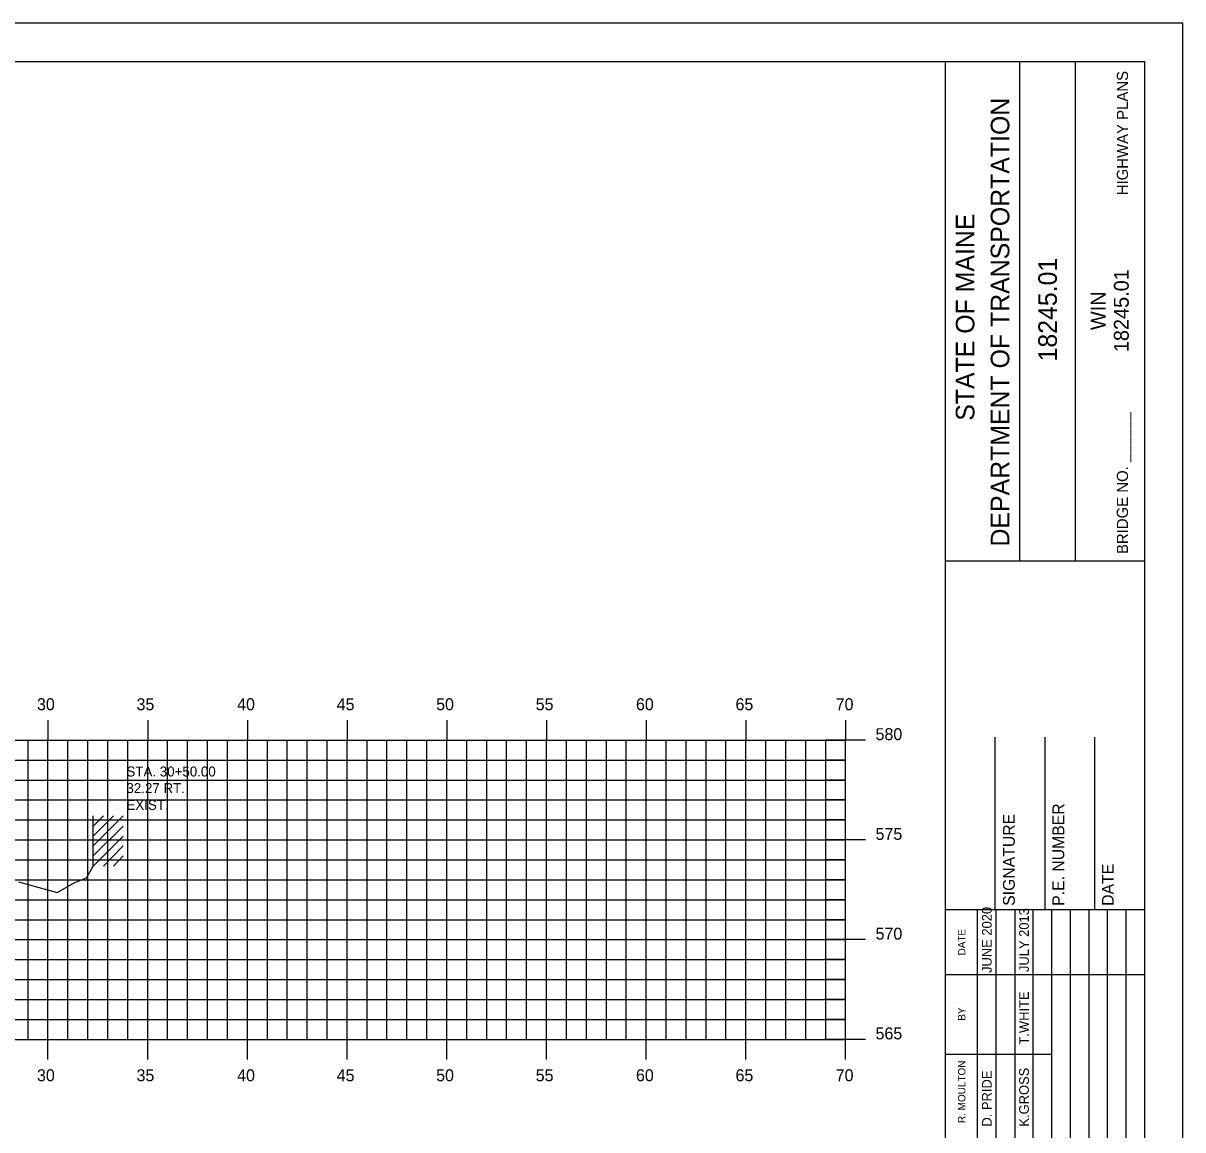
# Model space of a CAD drawing. Extents: x 1048109 to 1048279, y 781630 to 781740.
# Drawn here: x 1048220.5 to 1048278.6, y 781684.7 to 781740.1 of the extents above; entities that cross this region are included whole.
import ezdxf

# ---------------------------------------------------------------- set-up
doc = ezdxf.new("R2010")
doc.units = 0
for name, color, linetype in [('BORDER', 7, 'Continuous'), ('D_Text_Monospaced', 7, 'Continuous'), ('Default', 7, 'Continuous'), ('H_V ANNOTATION', 7, 'Continuous'), ('MAJOR', 7, 'Continuous'), ('MINOR', 7, 'Continuous'), ('S_Buildings', 7, 'Continuous'), ('S_Roadway_Centerline', 7, 'Continuous')]:
    doc.layers.add(name, color=color, linetype=linetype)

msp = doc.modelspace()

# ---------------------------------------------------------------- linework, layer by layer
at = {"layer": 'Default'}
for p, q in [((1048276.734, 781738.195), (1048116.734, 781738.195)), ((1048266.734, 781633.195), (1048266.734, 781738.198)), ((1048270.462, 781713.193), (1048270.462, 781738.193)), ((1048273.257, 781713.193), (1048273.257, 781738.193)), ((1048276.734, 781633.195), (1048276.734, 781738.195)), ((1048266.734, 781713.19), (1048276.734, 781713.19)), ((1048269.234, 781695.698), (1048269.234, 781704.346)), ((1048271.734, 781695.698), (1048271.734, 781704.346)), ((1048274.234, 781695.698), (1048274.234, 781704.346)), ((1048266.734, 781695.698), (1048276.734, 781695.698))]:
    msp.add_line(p, q, dxfattribs=at)
msp.add_lwpolyline([(1048108.64, 781630.136), (1048278.64, 781630.136), (1048278.64, 781740.136), (1048108.64, 781740.136)], close=True, dxfattribs=at)
for points in [[(1048268.348, 781692.448), (1048268.348, 781695.698)], [(1048269.281, 781678.201), (1048269.281, 781695.698)], [(1048270.213, 781695.698), (1048270.213, 781678.201)], [(1048271.144, 781678.201), (1048271.144, 781695.698)], [(1048272.076, 781678.201), (1048272.076, 781695.698)], [(1048273.008, 781678.201), (1048273.008, 781695.698)], [(1048273.939, 781678.201), (1048273.939, 781695.698)], [(1048274.871, 781678.201), (1048274.871, 781695.698)], [(1048275.803, 781678.201), (1048275.803, 781695.698)], [(1048268.349, 781678.201), (1048268.349, 781694.992)], [(1048266.734, 781692.448), (1048276.734, 781692.448)], [(1048266.734, 781688.448), (1048268.349, 781688.448)], [(1048268.348, 781688.448), (1048272.075, 781688.448)]]:
    msp.add_lwpolyline(points, dxfattribs=at)
at = {"layer": 'MAJOR'}
for p, q in [((1048221.733, 781705.197), (1048221.733, 781704.195)), ((1048221.733, 781705.197), (1048221.733, 781704.195)), ((1048226.733, 781705.197), (1048226.733, 781704.195)), ((1048226.733, 781705.197), (1048226.733, 781704.195)), ((1048231.733, 781705.197), (1048231.733, 781704.195)), ((1048231.733, 781705.197), (1048231.733, 781704.195)), ((1048236.733, 781705.197), (1048236.733, 781704.195)), ((1048236.733, 781705.197), (1048236.733, 781704.195)), ((1048241.733, 781705.197), (1048241.733, 781704.195)), ((1048241.733, 781705.197), (1048241.733, 781704.195)), ((1048246.733, 781705.197), (1048246.733, 781704.195)), ((1048246.733, 781705.197), (1048246.733, 781704.195)), ((1048251.733, 781705.197), (1048251.733, 781704.195)), ((1048251.733, 781705.197), (1048251.733, 781704.195)), ((1048256.733, 781705.197), (1048256.733, 781704.195)), ((1048256.733, 781705.197), (1048256.733, 781704.195)), ((1048261.733, 781705.197), (1048261.733, 781704.195)), ((1048261.733, 781705.197), (1048261.733, 781704.195)), ((1048121.733, 781704.195), (1048261.733, 781704.195)), ((1048121.733, 781704.195), (1048261.733, 781704.195)), ((1048121.733, 781704.195), (1048261.733, 781704.195)), ((1048121.733, 781704.195), (1048261.733, 781704.195)), ((1048221.733, 781689.195), (1048221.733, 781704.195)), ((1048221.733, 781689.195), (1048221.733, 781704.195)), ((1048226.733, 781689.195), (1048226.733, 781704.195)), ((1048226.733, 781689.195), (1048226.733, 781704.195)), ((1048231.733, 781689.195), (1048231.733, 781704.195)), ((1048231.733, 781689.195), (1048231.733, 781704.195)), ((1048236.733, 781689.195), (1048236.733, 781704.195)), ((1048236.733, 781689.195), (1048236.733, 781704.195)), ((1048241.733, 781689.195), (1048241.733, 781704.195)), ((1048241.733, 781689.195), (1048241.733, 781704.195)), ((1048246.733, 781689.195), (1048246.733, 781704.195)), ((1048246.733, 781689.195), (1048246.733, 781704.195)), ((1048251.733, 781689.195), (1048251.733, 781704.195)), ((1048251.733, 781689.195), (1048251.733, 781704.195)), ((1048256.733, 781689.195), (1048256.733, 781704.195)), ((1048256.733, 781689.195), (1048256.733, 781704.195)), ((1048262.735, 781704.195), (1048260.731, 781704.195)), ((1048262.735, 781704.195), (1048260.731, 781704.195)), ((1048261.733, 781689.195), (1048261.733, 781704.195)), ((1048261.733, 781689.195), (1048261.733, 781704.195)), ((1048261.733, 781689.195), (1048261.733, 781704.195)), ((1048261.733, 781689.195), (1048261.733, 781704.195)), ((1048121.733, 781699.195), (1048261.733, 781699.195)), ((1048121.733, 781699.195), (1048261.733, 781699.195)), ((1048262.735, 781699.195), (1048260.731, 781699.195)), ((1048262.735, 781699.195), (1048260.731, 781699.195)), ((1048121.733, 781694.195), (1048261.733, 781694.195)), ((1048121.733, 781694.195), (1048261.733, 781694.195)), ((1048262.735, 781694.195), (1048260.731, 781694.195)), ((1048262.735, 781694.195), (1048260.731, 781694.195)), ((1048121.733, 781689.195), (1048261.733, 781689.195)), ((1048121.733, 781689.195), (1048261.733, 781689.195)), ((1048121.733, 781689.195), (1048261.733, 781689.195)), ((1048121.733, 781689.195), (1048261.733, 781689.195)), ((1048221.733, 781688.193), (1048221.733, 781689.195)), ((1048221.733, 781688.193), (1048221.733, 781689.195)), ((1048226.733, 781688.193), (1048226.733, 781689.195)), ((1048226.733, 781688.193), (1048226.733, 781689.195)), ((1048231.733, 781688.193), (1048231.733, 781689.195)), ((1048231.733, 781688.193), (1048231.733, 781689.195)), ((1048236.733, 781688.193), (1048236.733, 781689.195)), ((1048236.733, 781688.193), (1048236.733, 781689.195)), ((1048241.733, 781688.193), (1048241.733, 781689.195)), ((1048241.733, 781688.193), (1048241.733, 781689.195)), ((1048246.733, 781688.193), (1048246.733, 781689.195)), ((1048246.733, 781688.193), (1048246.733, 781689.195)), ((1048251.733, 781688.193), (1048251.733, 781689.195)), ((1048251.733, 781688.193), (1048251.733, 781689.195)), ((1048256.733, 781688.193), (1048256.733, 781689.195)), ((1048256.733, 781688.193), (1048256.733, 781689.195)), ((1048262.735, 781689.195), (1048260.731, 781689.195)), ((1048262.735, 781689.195), (1048260.731, 781689.195)), ((1048261.733, 781688.193), (1048261.733, 781689.195)), ((1048261.733, 781688.193), (1048261.733, 781689.195))]:
    msp.add_line(p, q, dxfattribs=at)
at = {"layer": 'MINOR'}
for p, q in [((1048220.733, 781689.195), (1048220.733, 781704.195)), ((1048220.733, 781689.195), (1048220.733, 781704.195)), ((1048222.733, 781689.195), (1048222.733, 781704.195)), ((1048222.733, 781689.195), (1048222.733, 781704.195)), ((1048223.733, 781689.195), (1048223.733, 781704.195)), ((1048223.733, 781689.195), (1048223.733, 781704.195)), ((1048224.733, 781689.195), (1048224.733, 781704.195)), ((1048224.733, 781689.195), (1048224.733, 781704.195)), ((1048225.733, 781689.195), (1048225.733, 781704.195)), ((1048225.733, 781689.195), (1048225.733, 781704.195)), ((1048227.733, 781689.195), (1048227.733, 781704.195)), ((1048227.733, 781689.195), (1048227.733, 781704.195)), ((1048228.733, 781689.195), (1048228.733, 781704.195)), ((1048228.733, 781689.195), (1048228.733, 781704.195)), ((1048229.733, 781689.195), (1048229.733, 781704.195)), ((1048229.733, 781689.195), (1048229.733, 781704.195)), ((1048230.733, 781689.195), (1048230.733, 781704.195)), ((1048230.733, 781689.195), (1048230.733, 781704.195)), ((1048232.733, 781689.195), (1048232.733, 781704.195)), ((1048232.733, 781689.195), (1048232.733, 781704.195)), ((1048233.733, 781689.195), (1048233.733, 781704.195)), ((1048233.733, 781689.195), (1048233.733, 781704.195)), ((1048234.733, 781689.195), (1048234.733, 781704.195)), ((1048234.733, 781689.195), (1048234.733, 781704.195)), ((1048235.733, 781689.195), (1048235.733, 781704.195)), ((1048235.733, 781689.195), (1048235.733, 781704.195)), ((1048237.733, 781689.195), (1048237.733, 781704.195)), ((1048237.733, 781689.195), (1048237.733, 781704.195)), ((1048238.733, 781689.195), (1048238.733, 781704.195)), ((1048238.733, 781689.195), (1048238.733, 781704.195)), ((1048239.733, 781689.195), (1048239.733, 781704.195)), ((1048239.733, 781689.195), (1048239.733, 781704.195)), ((1048240.733, 781689.195), (1048240.733, 781704.195)), ((1048240.733, 781689.195), (1048240.733, 781704.195)), ((1048242.733, 781689.195), (1048242.733, 781704.195)), ((1048242.733, 781689.195), (1048242.733, 781704.195)), ((1048243.733, 781689.195), (1048243.733, 781704.195)), ((1048243.733, 781689.195), (1048243.733, 781704.195)), ((1048244.733, 781689.195), (1048244.733, 781704.195)), ((1048244.733, 781689.195), (1048244.733, 781704.195)), ((1048245.733, 781689.195), (1048245.733, 781704.195)), ((1048245.733, 781689.195), (1048245.733, 781704.195)), ((1048247.733, 781689.195), (1048247.733, 781704.195)), ((1048247.733, 781689.195), (1048247.733, 781704.195)), ((1048248.733, 781689.195), (1048248.733, 781704.195)), ((1048248.733, 781689.195), (1048248.733, 781704.195)), ((1048249.733, 781689.195), (1048249.733, 781704.195)), ((1048249.733, 781689.195), (1048249.733, 781704.195)), ((1048250.733, 781689.195), (1048250.733, 781704.195)), ((1048250.733, 781689.195), (1048250.733, 781704.195)), ((1048252.733, 781689.195), (1048252.733, 781704.195)), ((1048252.733, 781689.195), (1048252.733, 781704.195)), ((1048253.733, 781689.195), (1048253.733, 781704.195)), ((1048253.733, 781689.195), (1048253.733, 781704.195)), ((1048254.733, 781689.195), (1048254.733, 781704.195)), ((1048254.733, 781689.195), (1048254.733, 781704.195)), ((1048255.733, 781689.195), (1048255.733, 781704.195)), ((1048255.733, 781689.195), (1048255.733, 781704.195)), ((1048257.733, 781689.195), (1048257.733, 781704.195)), ((1048257.733, 781689.195), (1048257.733, 781704.195)), ((1048258.733, 781689.195), (1048258.733, 781704.195)), ((1048258.733, 781689.195), (1048258.733, 781704.195)), ((1048259.733, 781689.195), (1048259.733, 781704.195)), ((1048259.733, 781689.195), (1048259.733, 781704.195)), ((1048260.733, 781689.195), (1048260.733, 781704.195)), ((1048260.733, 781689.195), (1048260.733, 781704.195)), ((1048121.733, 781703.195), (1048261.733, 781703.195)), ((1048121.733, 781703.195), (1048261.733, 781703.195)), ((1048261.733, 781703.195), (1048260.731, 781703.195)), ((1048261.733, 781703.195), (1048260.731, 781703.195)), ((1048121.733, 781702.195), (1048261.733, 781702.195)), ((1048121.733, 781702.195), (1048261.733, 781702.195)), ((1048261.733, 781702.195), (1048260.731, 781702.195)), ((1048261.733, 781702.195), (1048260.731, 781702.195)), ((1048121.733, 781701.195), (1048261.733, 781701.195)), ((1048121.733, 781701.195), (1048261.733, 781701.195)), ((1048261.733, 781701.195), (1048260.731, 781701.195)), ((1048261.733, 781701.195), (1048260.731, 781701.195)), ((1048121.733, 781700.195), (1048261.733, 781700.195)), ((1048121.733, 781700.195), (1048261.733, 781700.195)), ((1048261.733, 781700.195), (1048260.731, 781700.195)), ((1048261.733, 781700.195), (1048260.731, 781700.195)), ((1048121.733, 781698.195), (1048261.733, 781698.195)), ((1048121.733, 781698.195), (1048261.733, 781698.195)), ((1048261.733, 781698.195), (1048260.731, 781698.195)), ((1048261.733, 781698.195), (1048260.731, 781698.195)), ((1048121.733, 781697.195), (1048261.733, 781697.195)), ((1048261.733, 781697.195), (1048260.731, 781697.195)), ((1048261.733, 781697.195), (1048260.731, 781697.195)), ((1048121.733, 781696.195), (1048261.733, 781696.195)), ((1048121.733, 781696.195), (1048261.733, 781696.195)), ((1048261.733, 781696.195), (1048260.731, 781696.195)), ((1048261.733, 781696.195), (1048260.731, 781696.195)), ((1048121.733, 781695.195), (1048261.733, 781695.195)), ((1048121.733, 781695.195), (1048261.733, 781695.195)), ((1048261.733, 781695.195), (1048260.731, 781695.195)), ((1048261.733, 781695.195), (1048260.731, 781695.195)), ((1048121.733, 781693.195), (1048261.733, 781693.195)), ((1048121.733, 781693.195), (1048261.733, 781693.195)), ((1048261.733, 781693.195), (1048260.731, 781693.195)), ((1048261.733, 781693.195), (1048260.731, 781693.195)), ((1048121.733, 781692.195), (1048261.733, 781692.195)), ((1048121.733, 781692.195), (1048261.733, 781692.195)), ((1048261.733, 781692.195), (1048260.731, 781692.195)), ((1048261.733, 781692.195), (1048260.731, 781692.195)), ((1048121.733, 781691.195), (1048261.733, 781691.195)), ((1048121.733, 781691.195), (1048261.733, 781691.195)), ((1048261.733, 781691.195), (1048260.731, 781691.195)), ((1048261.733, 781691.195), (1048260.731, 781691.195)), ((1048121.733, 781690.195), (1048261.733, 781690.195)), ((1048121.733, 781690.195), (1048261.733, 781690.195)), ((1048261.733, 781690.195), (1048260.731, 781690.195)), ((1048261.733, 781690.195), (1048260.731, 781690.195))]:
    msp.add_line(p, q, dxfattribs=at)
at = {"layer": 'S_Buildings'}
for p, q in [((1048224, 781697.876), (1048224, 781700.402)), ((1048224, 781698.893), (1048225.509, 781700.402)), ((1048224, 781699.385), (1048225.017, 781700.402)), ((1048224, 781699.877), (1048224.525, 781700.402)), ((1048224, 781698.401), (1048225.509, 781699.877)), ((1048224, 781697.876), (1048225.509, 781699.385)), ((1048224.525, 781697.876), (1048225.509, 781698.893)), ((1048225.017, 781697.876), (1048225.509, 781698.401))]:
    msp.add_line(p, q, dxfattribs=at)
at = {"layer": 'S_Roadway_Centerline'}
msp.add_lwpolyline([(1048220.247, 781697.091), (1048222.193, 781696.555), (1048223.072, 781697.058), (1048223.663, 781697.3), (1048224, 781697.876)], dxfattribs=at)

# ---------------------------------------------------------------- texts
at = {"layer": 'BORDER'}
for s, p in [('DEPARTMENT OF TRANSPORTATION', (1048269.94, 781713.901)), ('STATE OF MAINE', (1048268.189, 781720.207))]:
    msp.add_text(s, height=0.93176, rotation=90, dxfattribs=at).set_placement(p)
at = {"layer": 'D_Text_Monospaced'}
for s, height, p in [('STA. 30+50.00', 0.49998, (1048225.667, 781702.374)), ('32.27 RT.', 0.5, (1048225.667, 781701.54)), ('EXIST. ', 0.5, (1048225.667, 781700.7))]:
    msp.add_text(s, height=height, dxfattribs=at).set_placement(p)
at = {"layer": 'Default'}
for s, height, p in [('HIGHWAY PLANS', 0.55901, (1048275.892, 781731.511)), ('18245.01', 0.9318, (1048272.325, 781723.18)), ('18245.01', 0.7453, (1048275.929, 781723.646)), ('WIN', 0.7453, (1048274.77, 781724.753)), ('BRIDGE NO. ______', 0.55901, (1048275.892, 781713.526)), ('P.E. NUMBER', 0.59055, (1048272.694, 781695.891)), ('SIGNATURE', 0.5906, (1048270.214, 781695.891)), ('DATE', 0.5906, (1048275.175, 781695.891)), ('JUNE 2020', 0.4845, (1048269.056, 781692.524)), ('JULY 2013', 0.4845, (1048270.92, 781692.57)), ('DATE', 0.3714, (1048267.738, 781693.404)), ('T.WHITE', 0.4845, (1048270.92, 781688.934)), ('BY', 0.3714, (1048267.738, 781690.133)), ('R. MOULTON', 0.3727, (1048267.738, 781685.001)), ('D. PRIDE', 0.4845, (1048269.056, 781684.822)), ('K.GROSS', 0.4845, (1048270.92, 781684.822))]:
    msp.add_text(s, height=height, rotation=90, dxfattribs=at).set_placement(p)
at = {"layer": 'H_V ANNOTATION'}
for s, p in [('30', (1048221.182, 781705.695)), ('35', (1048226.174, 781705.695)), ('40', (1048231.219, 781705.695)), ('45', (1048236.211, 781705.695)), ('50', (1048241.198, 781705.695)), ('55', (1048246.19, 781705.695)), ('60', (1048251.219, 781705.695)), ('65', (1048256.211, 781705.695)), ('70', (1048261.235, 781705.695)), ('580', (1048263.233, 781704.195)), ('575', (1048263.233, 781699.195)), ('570', (1048263.233, 781694.195)), ('565', (1048263.233, 781689.195)), ('30', (1048221.182, 781687.095)), ('35', (1048226.174, 781687.095)), ('40', (1048231.219, 781687.095)), ('45', (1048236.211, 781687.095)), ('50', (1048241.198, 781687.095)), ('55', (1048246.19, 781687.095)), ('60', (1048251.219, 781687.095)), ('65', (1048256.211, 781687.095)), ('70', (1048261.235, 781687.095))]:
    msp.add_text(s, height=0.6, dxfattribs=at).set_placement(p)

doc.saveas('drawing.dxf')
